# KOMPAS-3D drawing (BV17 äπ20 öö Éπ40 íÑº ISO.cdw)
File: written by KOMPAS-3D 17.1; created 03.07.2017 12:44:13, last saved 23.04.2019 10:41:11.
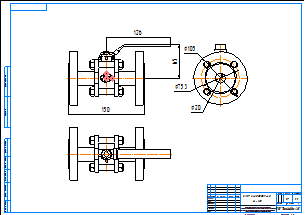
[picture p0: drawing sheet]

Sheet 1: A2, landscape

Title block, sheet 1: name: BV17 Ду20 ФФ Ру40 / без ISO; material: Внимание! Данный продукт является объектом авторского права ООО «Торговый Дом АДЛ». / Запрещается изменение, копирование, распространение / (в том числе путем копирования на другие сайты и ресурсы в Интернете) / или любое иное использование информации и объектов без предварительного / согласия правообладателя (ООО «Торговый Дом АДЛ»).; mass: 1,7; sheets: 1; organisation: ООО "Торговый дом АДЛ"; sheet format: A2; stored path: C:\Users\kka\KOMPAS_Work\!Trash\СС02 СС03 ФФ Смотровые стекла\СС01.cdw

Views: Спереди 1, Проекционный вид 2, Проекционный вид 3
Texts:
  Klimkovich
  ADL
Dimensions and other numbers on the sheet: 150; 126; 65; 75,3; 105; 20; 1:1; 1; 1,7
